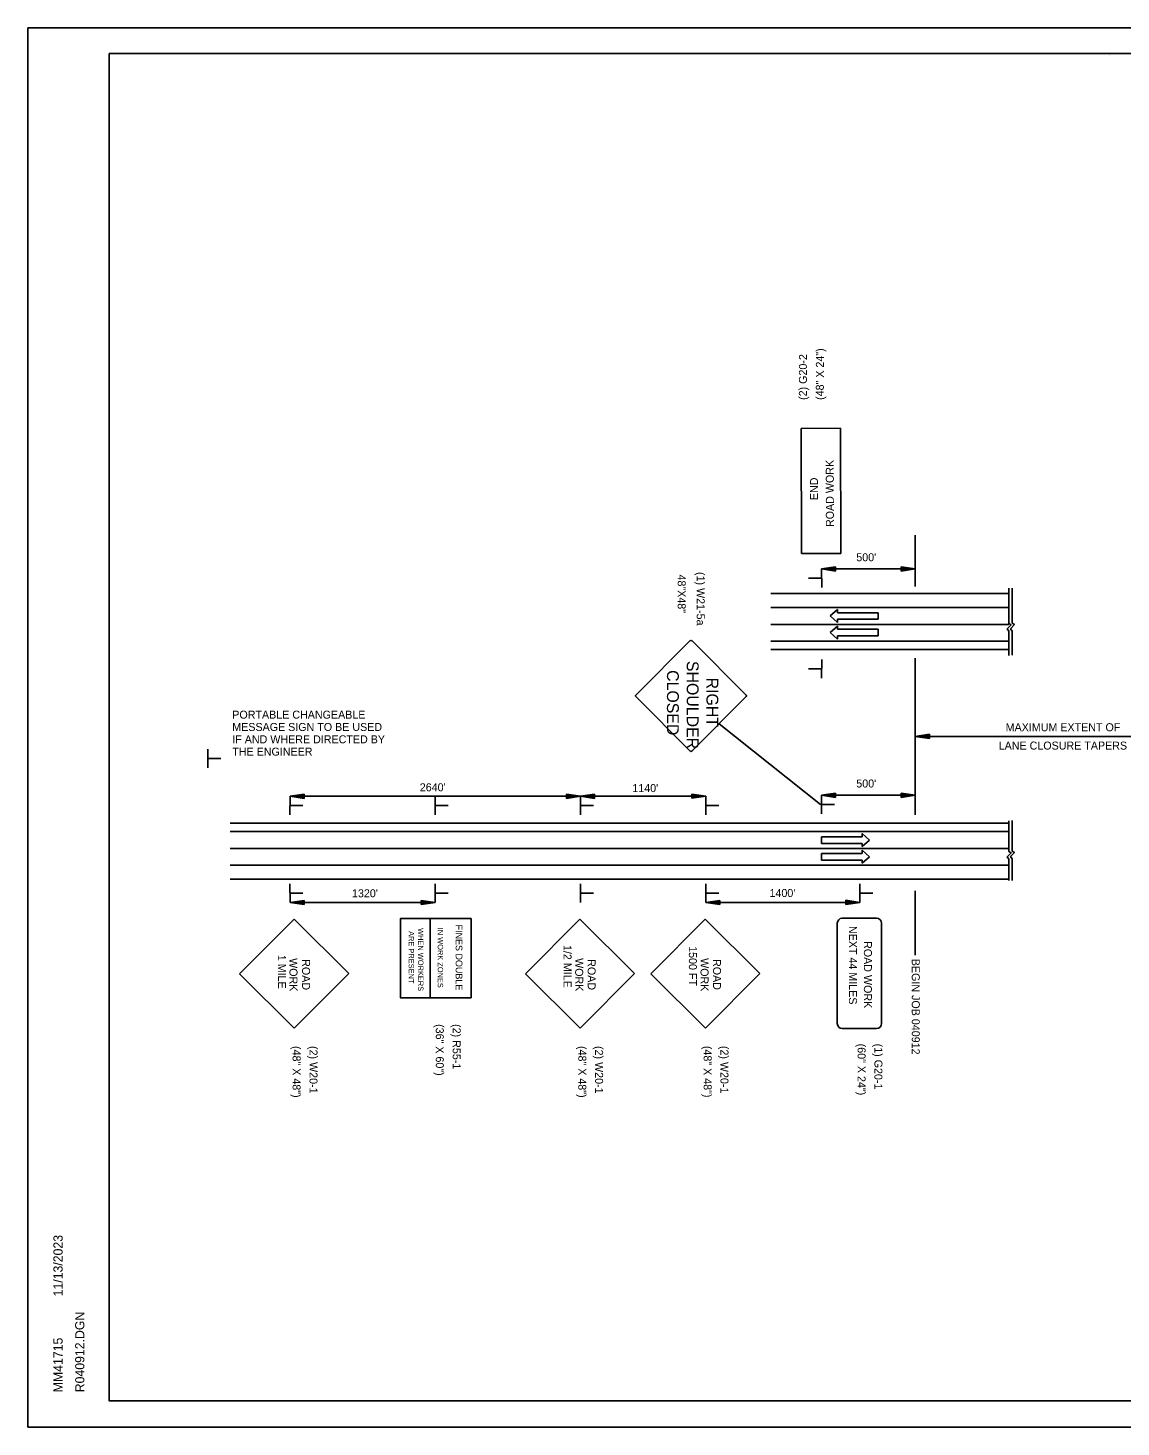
# Model space of a CAD drawing. Extents: x 13744624 to 13747958, y 3814079 to 3815145.
# Drawn here: x 13744624 to 13745458, y 3814079 to 3815145 of the extents above; entities that cross this region are included whole.
import ezdxf

# ---------------------------------------------------------------- set-up
doc = ezdxf.new("R2010")
doc.units = 0
for name, color, linetype in [('Default', 7, 'Continuous'), ('R_Border', 7, 'Continuous'), ('R_Draft', 7, 'Continuous'), ('R_MOT', 7, 'Continuous'), ('R_No Plot', 7, 'Continuous')]:
    doc.layers.add(name, color=color, linetype=linetype)

msp = doc.modelspace()

# ---------------------------------------------------------------- linework, layer by layer
at = {"layer": 'Default'}
for p, q in [((13745300.8, 3814719.6), (13745300.8, 3814758.8)), ((13745229.4, 3814732.9), (13745300.8, 3814732.9)), ((13745190.6, 3814714.3), (13745372.3, 3814714.3)), ((13745372.3, 3814691.3), (13745372.3, 3814718.2)), ((13745372.3, 3814691.3), (13745372.3, 3814718.2)), ((13745374.8, 3814691.5), (13745374.8, 3814718.4)), ((13745374.8, 3814691.5), (13745374.8, 3814718.4)), ((13745190.6, 3814703.6), (13745372.3, 3814703.6)), ((13745190.6, 3814690.7), (13745372.3, 3814690.7)), ((13745372.3, 3814666.9), (13745372.3, 3814685.4)), ((13745372.3, 3814666.9), (13745372.3, 3814685.4)), ((13745374.8, 3814667.1), (13745374.8, 3814685.6)), ((13745374.8, 3814667.1), (13745374.8, 3814685.6)), ((13745190.6, 3814677.9), (13745372.3, 3814677.9)), ((13745190.6, 3814671.4), (13745372.3, 3814671.4)), ((13745300.8, 3814665), (13745300.8, 3814545.5)), ((13745228.6, 3814553.4), (13745151.2, 3814614.8)), ((13745300.8, 3814605.3), (13745534.4, 3814605.3)), ((13745045.5, 3814559.6), (13744824.1, 3814559.6)), ((13745141.1, 3814559.7), (13745045.5, 3814559.6)), ((13745229.4, 3814560.5), (13745300.8, 3814560.5)), ((13745372.3, 3814517.5), (13745372.3, 3814541)), ((13745374.8, 3814517.7), (13745374.8, 3814541.2)), ((13744778.5, 3814539.1), (13745372.3, 3814539.1)), ((13744778.5, 3814532.7), (13745372.3, 3814532.7)), ((13744778.5, 3814519.8), (13745372.3, 3814519.8)), ((13745372.3, 3814495.3), (13745372.3, 3814511.7)), ((13745374.8, 3814495.5), (13745374.8, 3814511.8)), ((13744778.5, 3814507), (13745372.3, 3814507)), ((13744778.5, 3814496.3), (13745372.3, 3814496.3)), ((13745300.8, 3814487.6), (13745300.8, 3814438.5)), ((13744934.8, 3814478.6), (13744824.1, 3814478.6)), ((13745258.6, 3814478.6), (13745141.1, 3814478.6))]:
    msp.add_line(p, q, dxfattribs=at)
for points in [[(13745372.3, 3814691.3), (13745373.9, 3814690.3), (13745371, 3814687.2), (13745372.3, 3814685.4)], [(13745372.3, 3814691.3), (13745373.9, 3814690.3), (13745371, 3814687.2), (13745372.3, 3814685.4)], [(13745374.8, 3814691.5), (13745376.5, 3814690.5), (13745373.6, 3814687.4), (13745374.8, 3814685.6)], [(13745374.8, 3814691.5), (13745376.5, 3814690.5), (13745373.6, 3814687.4), (13745374.8, 3814685.6)], [(13745372.3, 3814517.5), (13745373.9, 3814516.5), (13745371, 3814513.5), (13745372.3, 3814511.7)], [(13745374.8, 3814517.7), (13745376.5, 3814516.7), (13745373.6, 3814513.7), (13745374.8, 3814511.8)]]:
    msp.add_lwpolyline(points, dxfattribs=at)
at = {"layer": 'R_Border'}
for p, q in [((13744686.2, 3815125.9), (13746267.1, 3815125.9)), ((13744686.2, 3814098.6), (13744686.2, 3815125.9)), ((13745448.8, 3815124.6), (13745448.8, 3815124.6)), ((13745448.8, 3815124.6), (13745448.8, 3815124.6)), ((13744686.2, 3814098.6), (13744686.2, 3814098.6)), ((13746267.1, 3814098.6), (13744686.2, 3814098.6))]:
    msp.add_line(p, q, dxfattribs=at)
at = {"layer": 'R_Draft'}
for p, q in [((13745240.1, 3814734.5), (13745229.4, 3814732.9)), ((13745240.1, 3814731.3), (13745229.4, 3814732.9)), ((13745240.1, 3814734.3), (13745231.2, 3814732.9)), ((13745240.1, 3814731.6), (13745231.2, 3814732.9)), ((13745240.1, 3814734), (13745233, 3814732.9)), ((13745240.1, 3814731.9), (13745233, 3814732.9)), ((13745240.1, 3814733.7), (13745234.8, 3814732.9)), ((13745240.1, 3814732.1), (13745234.8, 3814732.9)), ((13745240.1, 3814733.5), (13745236.6, 3814732.9)), ((13745240.1, 3814732.4), (13745236.6, 3814732.9)), ((13745240.1, 3814733.2), (13745238.4, 3814732.9)), ((13745240.1, 3814732.7), (13745238.4, 3814732.9)), ((13745240.1, 3814731.3), (13745240.1, 3814734.5)), ((13745290.1, 3814734.5), (13745300.8, 3814732.9)), ((13745290.1, 3814734.5), (13745290.1, 3814731.3)), ((13745290.1, 3814734.3), (13745299, 3814732.9)), ((13745290.1, 3814734), (13745297.2, 3814732.9)), ((13745290.1, 3814733.7), (13745295.4, 3814732.9)), ((13745290.1, 3814733.5), (13745293.6, 3814732.9)), ((13745290.1, 3814733.2), (13745291.8, 3814732.9)), ((13745290.1, 3814731.3), (13745300.8, 3814732.9)), ((13745290.1, 3814732.4), (13745293.6, 3814732.9)), ((13745290.1, 3814731.9), (13745297.2, 3814732.9)), ((13745290.1, 3814731.6), (13745299, 3814732.9)), ((13745290.1, 3814732.1), (13745295.4, 3814732.9)), ((13745290.1, 3814732.7), (13745291.8, 3814732.9)), ((13745087.8, 3814636.7), (13745129.3, 3814678.3)), ((13745130.4, 3814678.3), (13745172, 3814636.7)), ((13745129.3, 3814594), (13745087.8, 3814635.6)), ((13745172, 3814635.6), (13745130.4, 3814594)), ((13745311.6, 3814606.9), (13745300.8, 3814605.3)), ((13745311.6, 3814603.7), (13745300.8, 3814605.3)), ((13745311.6, 3814606.6), (13745302.6, 3814605.3)), ((13745311.6, 3814603.9), (13745302.6, 3814605.3)), ((13745311.6, 3814606.3), (13745304.5, 3814605.3)), ((13745311.6, 3814604.2), (13745304.5, 3814605.3)), ((13745311.6, 3814606.1), (13745306.3, 3814605.3)), ((13745311.6, 3814604.5), (13745306.3, 3814605.3)), ((13745311.6, 3814605.8), (13745308.1, 3814605.3)), ((13745311.6, 3814604.8), (13745308.1, 3814605.3)), ((13745311.6, 3814605.5), (13745309.9, 3814605.3)), ((13745311.6, 3814605), (13745309.9, 3814605.3)), ((13745311.6, 3814603.7), (13745311.6, 3814606.9)), ((13745240.1, 3814562.1), (13745229.4, 3814560.5)), ((13745240.1, 3814561.8), (13745231.2, 3814560.5)), ((13745240.1, 3814558.8), (13745240.1, 3814562.1)), ((13745290.1, 3814562.1), (13745300.8, 3814560.5)), ((13745290.1, 3814562.1), (13745290.1, 3814558.8)), ((13745290.1, 3814561.8), (13745299, 3814560.5)), ((13744834.8, 3814561.2), (13744824.1, 3814559.6)), ((13744834.8, 3814558), (13744824.1, 3814559.6)), ((13744834.8, 3814561), (13744825.9, 3814559.6)), ((13744834.8, 3814558.3), (13744825.9, 3814559.6)), ((13744834.8, 3814560.7), (13744827.7, 3814559.6)), ((13744834.8, 3814558.6), (13744827.7, 3814559.6)), ((13744834.8, 3814560.4), (13744829.5, 3814559.6)), ((13744834.8, 3814558.8), (13744829.5, 3814559.6)), ((13744834.8, 3814560.2), (13744831.3, 3814559.6)), ((13744834.8, 3814559.1), (13744831.3, 3814559.6)), ((13744834.8, 3814559.9), (13744833.1, 3814559.6)), ((13744834.8, 3814559.4), (13744833.1, 3814559.6)), ((13744834.8, 3814558), (13744834.8, 3814561.2)), ((13745034.8, 3814561.2), (13745045.5, 3814559.6)), ((13745034.8, 3814561.2), (13745034.8, 3814558)), ((13745034.8, 3814561), (13745043.7, 3814559.6)), ((13745034.8, 3814560.7), (13745041.9, 3814559.6)), ((13745034.8, 3814560.4), (13745040.1, 3814559.6)), ((13745034.8, 3814560.2), (13745038.3, 3814559.6)), ((13745034.8, 3814559.9), (13745036.5, 3814559.6)), ((13745034.8, 3814558), (13745045.5, 3814559.6)), ((13745034.8, 3814559.1), (13745038.3, 3814559.6)), ((13745034.8, 3814558.6), (13745041.9, 3814559.6)), ((13745034.8, 3814558.3), (13745043.7, 3814559.6)), ((13745034.8, 3814558.8), (13745040.1, 3814559.6)), ((13745034.8, 3814559.4), (13745036.5, 3814559.6)), ((13745056.2, 3814561.2), (13745045.5, 3814559.6)), ((13745056.2, 3814558), (13745045.5, 3814559.6)), ((13745056.2, 3814561), (13745047.3, 3814559.6)), ((13745056.2, 3814558.3), (13745047.3, 3814559.6)), ((13745056.2, 3814560.7), (13745049.2, 3814559.6)), ((13745056.2, 3814558.6), (13745049.2, 3814559.6)), ((13745056.2, 3814560.4), (13745050.9, 3814559.6)), ((13745056.2, 3814558.8), (13745050.9, 3814559.6)), ((13745056.2, 3814560.2), (13745052.8, 3814559.6)), ((13745056.2, 3814559.1), (13745052.8, 3814559.6)), ((13745056.2, 3814559.9), (13745054.5, 3814559.6)), ((13745056.2, 3814559.4), (13745054.5, 3814559.6)), ((13745056.2, 3814558), (13745056.2, 3814561.2)), ((13745130.4, 3814561.3), (13745141.1, 3814559.7)), ((13745130.4, 3814561.3), (13745130.4, 3814558.1)), ((13745130.4, 3814561), (13745139.3, 3814559.7)), ((13745130.4, 3814560.7), (13745137.5, 3814559.7)), ((13745130.4, 3814560.5), (13745135.7, 3814559.7)), ((13745130.4, 3814560.2), (13745133.9, 3814559.7)), ((13745130.4, 3814559.9), (13745132.1, 3814559.7)), ((13745130.4, 3814558.1), (13745141.1, 3814559.7)), ((13745130.4, 3814559.1), (13745133.9, 3814559.7)), ((13745130.4, 3814558.6), (13745137.5, 3814559.7)), ((13745130.4, 3814558.3), (13745139.3, 3814559.7)), ((13745130.4, 3814558.9), (13745135.7, 3814559.7)), ((13745130.4, 3814559.4), (13745132.1, 3814559.7)), ((13745240.1, 3814558.8), (13745229.4, 3814560.5)), ((13745240.1, 3814559.1), (13745231.2, 3814560.5)), ((13745240.1, 3814561.5), (13745233, 3814560.5)), ((13745240.1, 3814559.4), (13745233, 3814560.5)), ((13745240.1, 3814561.3), (13745234.8, 3814560.5)), ((13745240.1, 3814559.7), (13745234.8, 3814560.5)), ((13745240.1, 3814561), (13745236.6, 3814560.5)), ((13745240.1, 3814559.9), (13745236.6, 3814560.5)), ((13745240.1, 3814560.7), (13745238.4, 3814560.5)), ((13745240.1, 3814560.2), (13745238.4, 3814560.5)), ((13745290.1, 3814561.5), (13745297.2, 3814560.5)), ((13745290.1, 3814561.3), (13745295.4, 3814560.5)), ((13745290.1, 3814561), (13745293.6, 3814560.5)), ((13745290.1, 3814560.7), (13745291.8, 3814560.5)), ((13745290.1, 3814558.8), (13745300.8, 3814560.5)), ((13745290.1, 3814559.9), (13745293.6, 3814560.5)), ((13745290.1, 3814559.4), (13745297.2, 3814560.5)), ((13745290.1, 3814559.1), (13745299, 3814560.5)), ((13745290.1, 3814559.7), (13745295.4, 3814560.5)), ((13745290.1, 3814560.2), (13745291.8, 3814560.5)), ((13744834.8, 3814480.2), (13744824.1, 3814478.6)), ((13744834.8, 3814477), (13744824.1, 3814478.6)), ((13744834.8, 3814479.9), (13744825.9, 3814478.6)), ((13744834.8, 3814477.3), (13744825.9, 3814478.6)), ((13744834.8, 3814479.7), (13744827.7, 3814478.6)), ((13744834.8, 3814477.5), (13744827.7, 3814478.6)), ((13744834.8, 3814479.4), (13744829.5, 3814478.6)), ((13744834.8, 3814477.8), (13744829.5, 3814478.6)), ((13744834.8, 3814479.1), (13744831.3, 3814478.6)), ((13744834.8, 3814478.1), (13744831.3, 3814478.6)), ((13744834.8, 3814478.8), (13744833.1, 3814478.6)), ((13744834.8, 3814478.3), (13744833.1, 3814478.6)), ((13744834.8, 3814477), (13744834.8, 3814480.2)), ((13744924.1, 3814480.2), (13744934.8, 3814478.6)), ((13744924.1, 3814480.2), (13744924.1, 3814477)), ((13744924.1, 3814479.9), (13744933, 3814478.6)), ((13744924.1, 3814479.7), (13744931.2, 3814478.6)), ((13744924.1, 3814479.4), (13744929.4, 3814478.6)), ((13744924.1, 3814479.1), (13744927.6, 3814478.6)), ((13744924.1, 3814478.8), (13744925.8, 3814478.6)), ((13744924.1, 3814477), (13744934.8, 3814478.6)), ((13744924.1, 3814478.1), (13744927.6, 3814478.6)), ((13744924.1, 3814477.5), (13744931.2, 3814478.6)), ((13744924.1, 3814477.3), (13744933, 3814478.6)), ((13744924.1, 3814477.8), (13744929.4, 3814478.6)), ((13744924.1, 3814478.3), (13744925.8, 3814478.6)), ((13745151.8, 3814480.2), (13745141.1, 3814478.6)), ((13745151.8, 3814477), (13745141.1, 3814478.6)), ((13745151.8, 3814480), (13745142.9, 3814478.6)), ((13745151.8, 3814477.3), (13745142.9, 3814478.6)), ((13745151.8, 3814479.7), (13745144.8, 3814478.6)), ((13745151.8, 3814477.6), (13745144.8, 3814478.6)), ((13745151.8, 3814479.4), (13745146.5, 3814478.6)), ((13745151.8, 3814477.8), (13745146.5, 3814478.6)), ((13745151.8, 3814479.1), (13745148.4, 3814478.6)), ((13745151.8, 3814478.1), (13745148.4, 3814478.6)), ((13745151.8, 3814478.9), (13745150.2, 3814478.6)), ((13745151.8, 3814478.4), (13745150.2, 3814478.6)), ((13745151.8, 3814477), (13745151.8, 3814480.2)), ((13745247.8, 3814480.3), (13745258.6, 3814478.6)), ((13745247.8, 3814480.3), (13745247.8, 3814477)), ((13745247.8, 3814480), (13745256.8, 3814478.6)), ((13745247.8, 3814479.7), (13745254.9, 3814478.6)), ((13745247.8, 3814479.4), (13745253.1, 3814478.6)), ((13745247.8, 3814479.2), (13745251.3, 3814478.6)), ((13745247.8, 3814478.9), (13745249.5, 3814478.6)), ((13745247.8, 3814477), (13745258.6, 3814478.6)), ((13745247.8, 3814478.1), (13745251.3, 3814478.6)), ((13745247.8, 3814477.6), (13745254.9, 3814478.6)), ((13745247.8, 3814477.3), (13745256.8, 3814478.6)), ((13745247.8, 3814477.8), (13745253.1, 3814478.6)), ((13745247.8, 3814478.4), (13745249.5, 3814478.6))]:
    msp.add_line(p, q, dxfattribs=at)
for centre, start, end in [((13745129.9, 3814677.7), 45, 134.9999), ((13745088.3, 3814636.2), 134.9999, 225.0001), ((13745171.5, 3814636.2), 315, 45), ((13745129.9, 3814594.6), 225.0001, 315)]:
    msp.add_arc(centre, 0.754, start, end, dxfattribs=at)
at = {"layer": 'R_MOT'}
for p, q in [((13745243.9, 3814840.2), (13745213.9, 3814840.1)), ((13745213.9, 3814840.1), (13745214.1, 3814744.8)), ((13745243.9, 3814840.2), (13745244.1, 3814744.8)), ((13745244.1, 3814744.8), (13745214.1, 3814744.8)), ((13745229.4, 3814732.9), (13745229.5, 3814718.8)), ((13745229.4, 3814725.9), (13745219.5, 3814725.8)), ((13745241.5, 3814702.1), (13745236, 3814697.1)), ((13745241.5, 3814699.6), (13745241.5, 3814702.1)), ((13745236, 3814697.1), (13745241.5, 3814692.1)), ((13745272.7, 3814699.6), (13745241.5, 3814699.6)), ((13745241.5, 3814692.1), (13745241.5, 3814694.6)), ((13745241.5, 3814694.6), (13745272.7, 3814694.6)), ((13745272.7, 3814694.6), (13745272.7, 3814699.6)), ((13745236, 3814684.4), (13745241.5, 3814689.4)), ((13745241.5, 3814679.4), (13745236, 3814684.4)), ((13745241.5, 3814689.4), (13745241.5, 3814686.9)), ((13745241.5, 3814686.9), (13745272.7, 3814686.9)), ((13745272.7, 3814681.9), (13745241.5, 3814681.9)), ((13745241.5, 3814681.9), (13745241.5, 3814679.4)), ((13745272.7, 3814686.9), (13745272.7, 3814681.9)), ((13745229.4, 3814649.7), (13745229.5, 3814663.9)), ((13745229.4, 3814656.8), (13745219.5, 3814656.8)), ((13744761.3, 3814581.4), (13744761.3, 3814595.6)), ((13744761.3, 3814588.5), (13744771.2, 3814588.5)), ((13744824.1, 3814559.6), (13744824, 3814545.5)), ((13744824.1, 3814552.6), (13744833.9, 3814552.5)), ((13744934.8, 3814559.6), (13744934.7, 3814545.5)), ((13744934.8, 3814552.6), (13744944.7, 3814552.5)), ((13745045.5, 3814559.6), (13745045.5, 3814545.5)), ((13745045.5, 3814552.6), (13745055.4, 3814552.5)), ((13745141.1, 3814559.6), (13745141.1, 3814545.4)), ((13745141.1, 3814552.6), (13745151, 3814552.5)), ((13745229.4, 3814560.5), (13745229.3, 3814546.3)), ((13745229.4, 3814553.4), (13745239.2, 3814553.4)), ((13745260.5, 3814528.7), (13745260.5, 3814531.2)), ((13745260.5, 3814531.2), (13745266, 3814526.2)), ((13745229.3, 3814528.7), (13745260.5, 3814528.7)), ((13745229.3, 3814523.7), (13745229.3, 3814528.7)), ((13745260.5, 3814523.7), (13745229.3, 3814523.7)), ((13745266, 3814526.2), (13745260.5, 3814521.2)), ((13745260.5, 3814521.2), (13745260.5, 3814523.7)), ((13745260.5, 3814516), (13745229.3, 3814516)), ((13745229.3, 3814516), (13745229.3, 3814511)), ((13745229.3, 3814511), (13745260.5, 3814511)), ((13745266, 3814513.5), (13745260.5, 3814518.5)), ((13745260.5, 3814518.5), (13745260.5, 3814516)), ((13745260.5, 3814508.5), (13745266, 3814513.5)), ((13745260.5, 3814511), (13745260.5, 3814508.5)), ((13744824.1, 3814478.6), (13744824, 3814492.8)), ((13744934.8, 3814478.6), (13744934.7, 3814492.8)), ((13745045.5, 3814478.6), (13745045.5, 3814492.8)), ((13745141.1, 3814478.6), (13745141.1, 3814492.8)), ((13745258.6, 3814478.6), (13745258.5, 3814492.8)), ((13744824.1, 3814485.7), (13744833.9, 3814485.7)), ((13744934.8, 3814485.7), (13744944.7, 3814485.7)), ((13745045.5, 3814485.7), (13745055.4, 3814485.7)), ((13745141.1, 3814485.7), (13745151, 3814485.7)), ((13745258.5, 3814485.7), (13745268.4, 3814485.7)), ((13744785.6, 3814424.2), (13744827.2, 3814465.9)), ((13744868.8, 3814424.4), (13744827.2, 3814465.9)), ((13744930.8, 3814406), (13744930.8, 3814466.3)), ((13745003.5, 3814424.2), (13745045, 3814465.9)), ((13745086.7, 3814424.4), (13745045, 3814465.9)), ((13745099.1, 3814424.3), (13745140.6, 3814466)), ((13745182.3, 3814424.4), (13745140.6, 3814466)), ((13745245.1, 3814466.6), (13745271.4, 3814466.6)), ((13745241.4, 3814386.3), (13745241.4, 3814462.9)), ((13745275.1, 3814386.3), (13745275.1, 3814462.9)), ((13744827.3, 3814382.7), (13744785.6, 3814424.2)), ((13744827.3, 3814382.7), (13744868.8, 3814424.4)), ((13745045.2, 3814382.7), (13745003.5, 3814424.2)), ((13745045.2, 3814382.7), (13745086.7, 3814424.4)), ((13745140.8, 3814382.7), (13745099.1, 3814424.3)), ((13745140.8, 3814382.7), (13745182.3, 3814424.4)), ((13745245.1, 3814382.6), (13745271.4, 3814382.6))]:
    msp.add_line(p, q, dxfattribs=at)
msp.add_lwpolyline([(13744962.1, 3814466.3), (13744908.2, 3814466.3), (13744908.2, 3814406), (13744962.1, 3814406)], close=True, dxfattribs=at)
for centre, start, end in [((13745245.1, 3814462.9), 90, 180), ((13745271.4, 3814462.9), 0, 90), ((13745245.1, 3814386.3), 180, 270), ((13745271.4, 3814386.3), 270, 0)]:
    msp.add_arc(centre, 3.69, start, end, dxfattribs=at)
at = {"layer": 'R_No Plot'}
for p, q in [((13744624.2, 3815145.4), (13746290.9, 3815145.4)), ((13744624.2, 3814078.7), (13746290.9, 3814078.7))]:
    msp.add_line(p, q, dxfattribs=at)
for points in [[(13744624.2, 3815145.4), (13746290.9, 3815145.4), (13746290.9, 3814078.7), (13744624.2, 3814078.7)], [(13745855.8, 3815125.9), (13745953.9, 3815125.9), (13745953.9, 3815076.5), (13746034.5, 3815076.5), (13746150.5, 3815076.5), (13746150.5, 3814954.9), (13746267.1, 3814954.9), (13746267.1, 3814098.6), (13744686.2, 3814098.6), (13744686.2, 3815125.9)]]:
    msp.add_lwpolyline(points, close=True, dxfattribs=at)

# ---------------------------------------------------------------- texts
at = {"layer": 'Default'}
for s, p in [("500'", (13745255.9, 3814738.8)), ('PORTABLE CHANGEABLE', (13744780, 3814618.8)), ('MESSAGE SIGN TO BE USED', (13744780, 3814609.4)), ('MAXIMUM EXTENT OF ', (13745369.8, 3814609.2)), ('IF AND WHERE DIRECTED BY', (13744780, 3814600)), ('THE ENGINEER', (13744780, 3814590.6)), ('LANE CLOSURE TAPERS', (13745364.5, 3814595.2)), ("500'", (13745255.9, 3814566.3)), ("2640'", (13744923, 3814563.4)), ("1140'", (13745085.1, 3814562.8)), ("1320'", (13744871.3, 3814482.6)), ("1400'", (13745189.7, 3814482.8))]:
    msp.add_text(s, height=6.1, dxfattribs=at).set_placement(p)
msp.add_text('BEGIN JOB 040912', height=6.1, rotation=270, dxfattribs=at).set_placement((13745298.2, 3814435.7))
at = {"layer": 'R_Border'}
for s, p in [('11/13/2023', (13744650.6, 3814178.3)), ('R040912.DGN', (13744667.2, 3814105.2)), ('MM41715', (13744650.6, 3814105.2))]:
    msp.add_text(s, height=7, rotation=90, dxfattribs=at).set_placement(p)
at = {"layer": 'R_Draft'}
for s, height, p in [('48"X48"', 6.1, (13745119.7, 3814728.7)), ('(1) W21-5a', 6.1, (13745134.2, 3814730.6)), ('SHOULDER', 9.05, (13745126.6, 3814662.8)), ('CLOSED', 9.05, (13745111.5, 3814655.8)), ('RIGHT', 9.05, (13745141.6, 3814650.1))]:
    msp.add_text(s, height=height, rotation=270, dxfattribs=at).set_placement(p)
at = {"layer": 'R_MOT'}
for s, height, rotation, p in [('(2) G20-2', 6.1, 89.7913, (13745218.2, 3814861.8)), ('(48" X 24")', 6.1, 89.7913, (13745231.1, 3814861.8)), ('ROAD WORK', 6.1, 90.0992, (13745238.8, 3814764.9)), ('END', 6.1, 90.0992, (13745226.7, 3814785.4)), ('ARE PRESENT', 4.094, 270, (13744914.5, 3814456.8)), ('WHEN WORKERS', 4.094, 270, (13744921.7, 3814459.1)), ('IN WORK ZONES', 4.093, 270, (13744936.7, 3814459.4)), ('FINES DOUBLE', 5.117, 270, (13744950.4, 3814461.8)), (' NEXT 44 MILES', 6.1, 270, (13745250.3, 3814463)), (' 1/2 MILE', 6.1, 270.0995, (13745032.6, 3814448.5)), (' 1500 FT', 6.1, 270.0995, (13745128.2, 3814447.6)), ('ROAD WORK', 6.1, 270, (13745261.7, 3814449.2)), (' 1 MILE', 6.1, 270.0995, (13744814.8, 3814441)), ('WORK', 6.1, 270.1003, (13744823.6, 3814436.2)), ('ROAD', 6.1, 270.1004, (13744833.2, 3814435.4)), ('WORK', 6.1, 270.1003, (13745041.5, 3814436.2)), ('ROAD', 6.1, 270.1004, (13745051, 3814435.4)), ('WORK', 6.1, 270.1003, (13745137.1, 3814436.2)), ('ROAD', 6.1, 270.1004, (13745146.6, 3814435.5)), ('(36" X 60")', 6.1, 270, (13744935.2, 3814385.9)), ('(2) R55-1', 6.1, 270, (13744948.1, 3814385.9)), ('(60" X 24")', 6.1, 270, (13745256.9, 3814371)), ('(1) G20-1', 6.1, 270, (13745269.7, 3814371)), ('(48" X 48")', 6.1, 270, (13744826, 3814369.2)), ('(2) W20-1', 6.1, 270, (13744838.9, 3814369.2)), ('(48" X 48")', 6.1, 270, (13745043.9, 3814369.2)), ('(2) W20-1', 6.1, 270, (13745056.7, 3814369.2)), ('(48" X 48")', 6.1, 270, (13745139.5, 3814369.3)), ('(2) W20-1', 6.1, 270, (13745152.3, 3814369.3))]:
    msp.add_text(s, height=height, rotation=rotation, dxfattribs=at).set_placement(p)

doc.saveas('drawing.dxf')
